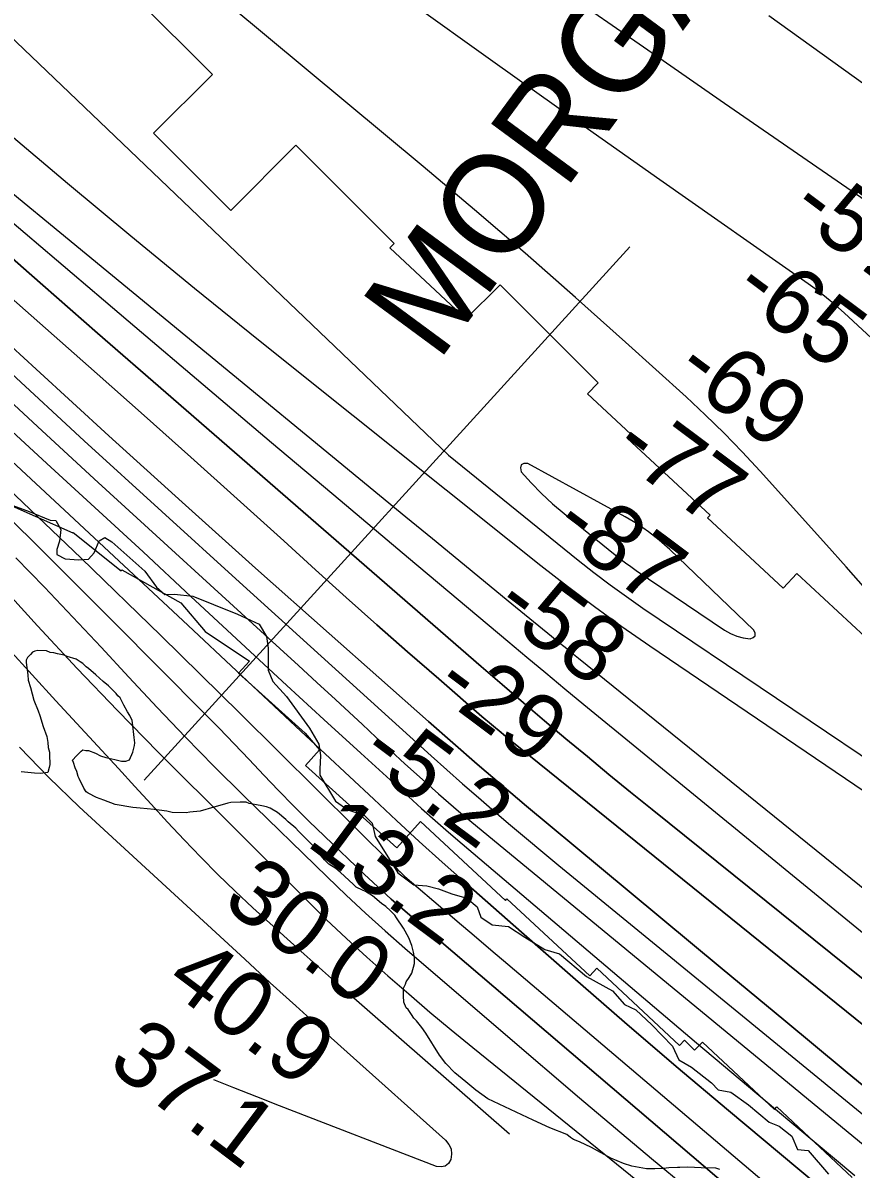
# Model space of a CAD drawing. Extents: x 3187622 to 3225504, y 800805 to 826213.
# Drawn here: x 3200680 to 3201516, y 814862 to 816017 of the extents above; entities that cross this region are included whole.
import ezdxf

# ---------------------------------------------------------------- set-up
doc = ezdxf.new("R2010")
doc.units = 0
for name, color, linetype in [('V-RIVR-EDGE', 7, 'Continuous'), ('V-RIVR-RANG', 7, 'Continuous'), ('V-RRAP-RVMT', 7, 'Continuous'), ('V-SITE-VEGE', 7, 'Continuous'), ('V-TOPO-DPTH', 7, 'Continuous'), ('V-TOPO-GNAM-IDEN', 7, 'Continuous'), ('V-TOPO-MAJR', 7, 'Continuous'), ('V-TOPO-MINR', 7, 'Continuous'), ('V-TOPO-WATR', 7, 'Continuous')]:
    doc.layers.add(name, color=color, linetype=linetype)

msp = doc.modelspace()

# ---------------------------------------------------------------- linework, layer by layer
at = {"layer": 'V-RIVR-EDGE'}
for points in [[(3200646.3, 815538.9), (3200685.8, 815524.5), (3200707.1, 815515.8), (3200712.8, 815515.3), (3200718, 815506.2), (3200716.6, 815494.4), (3200714, 815486.2), (3200714, 815481), (3200722.2, 815476.6), (3200736.1, 815475.7), (3200745.7, 815476.5), (3200751.4, 815482.6), (3200756.6, 815494.8), (3200762.3, 815498.2), (3200769.2, 815493.9), (3200802.6, 815464.2), (3200814.3, 815448.1), (3200822.5, 815440.7), (3200832.5, 815441.1), (3200850.8, 815438.9)], [(3200850.8, 815438.9), (3200871.6, 815430.6), (3200896, 815421), (3200917.7, 815410.9), (3200925, 815398.3), (3200926.7, 815386.5), (3200926.7, 815364.4), (3200931.4, 815353.1), (3200945.3, 815337.8), (3200968.3, 815306), (3200977.8, 815289.9), (3200979.5, 815278.6), (3200979, 815264.7), (3200979, 815258.6), (3200994.6, 815232.5), (3201007.2, 815223.8), (3201023.7, 815218.1), (3201031.5, 815210.2), (3201034.5, 815196.8), (3201057.5, 815160.2), (3201073.5, 815148), (3201086.5, 815147.1), (3201098.3, 815144), (3201111.7, 815139.2), (3201126.9, 815134.8), (3201137.3, 815126.1), (3201141.2, 815115.6), (3201152.5, 815107.8), (3201169, 815106), (3201185.5, 815095.5), (3201205.5, 815082.9), (3201220.3, 815078.5), (3201247.6, 815055.8), (3201273.6, 815041.4), (3201285.8, 815027.5), (3201297.1, 815022.2), (3201313.5, 815007), (3201334.3, 814985.6), (3201340.4, 814971.7), (3201353.4, 814964.3), (3201373.4, 814948.6), (3201380.3, 814941.6), (3201392.9, 814939), (3201410.7, 814926.3), (3201431.5, 814908.9), (3201441.5, 814905), (3201454.5, 814894.9), (3201460.1, 814881.4), (3201471, 814880.5), (3201491.4, 814856.6)]]:
    msp.add_lwpolyline(points, dxfattribs=at)
at = {"layer": 'V-RIVR-RANG'}
msp.add_line((3200801.9, 815253.6), (3201291.3, 815791.3), dxfattribs=at)
at = {"layer": 'V-RRAP-RVMT'}
for p, q in [((3200870.7, 815965), (3200793.6, 816042.1)), ((3200811.3, 815905.6), (3200870.7, 815965)), ((3200889.1, 815827.8), (3200811.3, 815905.6)), ((3200954.7, 815893.5), (3200889.1, 815827.8)), ((3201053.8, 815794.5), (3200954.7, 815893.5)), ((3201049.2, 815790), (3201053.8, 815794.5)), ((3201126, 815718.6), (3201049.2, 815790)), ((3201160.4, 815753), (3201126, 815718.6)), ((3201259.4, 815654.1), (3201160.4, 815753)), ((3201248.4, 815643.1), (3201259.4, 815654.1)), ((3201292.2, 815602.3), (3201248.4, 815643.1)), ((3201288.6, 815598.4), (3201292.2, 815602.3)), ((3201372, 815520.7), (3201288.6, 815598.4)), ((3200582.6, 815568.1), (3200730.1, 815503)), ((3201369.6, 815518.1), (3201372, 815520.7)), ((3201445.6, 815447.1), (3201369.6, 815518.1)), ((3200730.1, 815503), (3200730.2, 815503.3)), ((3200730.2, 815503.3), (3200778.6, 815464.7)), ((3200778.6, 815464.7), (3200779.4, 815465.6)), ((3200779.4, 815465.6), (3200838.7, 815432.5)), ((3201459.5, 815462), (3201445.6, 815447.1)), ((3201542.9, 815384.3), (3201459.5, 815462)), ((3200838.7, 815432.5), (3200863.4, 815403.3)), ((3200863.4, 815403.3), (3200908, 815373.6)), ((3200908, 815373.6), (3200897, 815361.6)), ((3200897, 815361.6), (3200964.2, 815300.9)), ((3200964.2, 815300.9), (3200978.6, 815284.2)), ((3200978.6, 815284.2), (3200964.3, 815268.3)), ((3200964.3, 815268.3), (3201056.3, 815185.3)), ((3201056.3, 815185.3), (3201080.4, 815212)), ((3201080.4, 815212), (3201165.8, 815132.4)), ((3201165.8, 815132.4), (3201167.4, 815134.1)), ((3201167.4, 815134.1), (3201250.8, 815056.4)), ((3201250.8, 815056.4), (3201257.9, 815064)), ((3201257.9, 815064), (3201341.2, 814986.2)), ((3201341.2, 814986.2), (3201346.3, 814991.7)), ((3201346.3, 814991.7), (3201356.5, 814981.5)), ((3201356.5, 814981.5), (3201364.5, 814989.5)), ((3201364.5, 814989.5), (3201437.1, 814921.8)), ((3201437.1, 814921.8), (3201439.3, 814924.2)), ((3201439.3, 814924.2), (3201515.3, 814853.3))]:
    msp.add_line(p, q, dxfattribs=at)
at = {"layer": 'V-SITE-VEGE'}
for points in [[(3201073.2, 815080.4), (3201071.4, 815087.1), (3201068.5, 815094.6), (3201063.2, 815104.5), (3201056.1, 815115), (3201054.3, 815117.5), (3201050.1, 815121.9), (3201045.2, 815126.3), (3201041, 815129.4), (3201032, 815136.9), (3201024.7, 815141.4), (3201021.7, 815142.6), (3201015.6, 815145.8), (3201012.6, 815148.3), (3200999.3, 815160.8), (3200995.1, 815164.6), (3200987.9, 815169), (3200983.6, 815173.4), (3200978.9, 815179), (3200972.3, 815187.1), (3200957.2, 815202.1), (3200954.8, 815205.2), (3200947, 815211.5), (3200944.6, 815214), (3200936.2, 815220.9), (3200928.9, 815225.3), (3200925.2, 815226.6), (3200920.4, 815227.9), (3200914.9, 815228.7), (3200907.5, 815230), (3200904.5, 815231.3), (3200898.4, 815231.4), (3200889.2, 815231), (3200886.1, 815230.4), (3200880.5, 815228.7), (3200871.9, 815226.4), (3200858.4, 815222.4), (3200847.9, 815221.4), (3200844.2, 815220.8), (3200830.2, 815221.1), (3200824.7, 815222.4), (3200811.8, 815223.9), (3200797.8, 815225.4), (3200790.4, 815226.2), (3200772.7, 815229), (3200761.1, 815233.5), (3200753.8, 815236.1), (3200745.4, 815240.5), (3200743.5, 815241.8), (3200741.2, 815245.5), (3200736.4, 815255.4), (3200735.3, 815257.2), (3200734.1, 815262.2), (3200732.4, 815265.9), (3200730.6, 815271.4), (3200729.5, 815273.9), (3200733.8, 815278.1), (3200738.2, 815282.9), (3200740.1, 815284.1), (3200743.1, 815283.4), (3200745.6, 815283.4), (3200752.9, 815280.8), (3200757.7, 815278.3), (3200763.2, 815276.3), (3200772.4, 815274.3), (3200779.1, 815272.9), (3200783.4, 815272.9), (3200787.1, 815274), (3200790.3, 815281.9), (3200792.2, 815288.6), (3200792.3, 815291.1), (3200791.8, 815296.6), (3200790.2, 815311.3), (3200789.7, 815313.8), (3200787.3, 815318.7), (3200784.9, 815322.5), (3200781.4, 815329.3), (3200777.8, 815336.7), (3200775.4, 815338.6), (3200773.6, 815341.1), (3200769.4, 815345.4), (3200765.8, 815348.6), (3200760.4, 815353), (3200753.2, 815359.8), (3200745.9, 815366.1), (3200743.5, 815368), (3200739.9, 815371.1), (3200737.5, 815373), (3200733.3, 815375.6), (3200724.1, 815378.2), (3200721.1, 815379.5), (3200714.4, 815380.8), (3200710.7, 815382.1), (3200707, 815382.2), (3200703.4, 815384.1), (3200694.8, 815384.3), (3200691.7, 815383.7), (3200689.3, 815382.5), (3200687.4, 815380.1), (3200684.3, 815377.1), (3200683, 815374.7)], [(3200683, 815374.7), (3200682.9, 815372.2), (3200683.5, 815367.3), (3200684.5, 815359.9), (3200685, 815354.4), (3200687.4, 815347), (3200690.8, 815334.1), (3200694.9, 815323.6), (3200696.6, 815318.7), (3200700.1, 815307.6), (3200703.6, 815297.7), (3200704.7, 815291.5), (3200705.2, 815286.6), (3200706.3, 815281.7), (3200706.3, 815279.3), (3200706.7, 815269.4), (3200706, 815266.4), (3200704.7, 815261.5), (3200697.3, 815260.4), (3200691.2, 815260.6), (3200677.8, 815262)], [(3201382, 814861.2), (3201377.8, 814862.5), (3201363.1, 814862.8), (3201349.6, 814863.6), (3201341.6, 814863.2), (3201339.2, 814863.2), (3201330.6, 814862.8), (3201325.1, 814862.3), (3201316.5, 814861.8), (3201307.9, 814862), (3201293.3, 814864.7), (3201284.7, 814867.3), (3201272, 814872.5), (3201258.6, 814880.1), (3201252.6, 814883.3), (3201240.4, 814889), (3201234.3, 814891.6), (3201231.3, 814893.5), (3201227.7, 814896.6), (3201210.7, 814903.1), (3201193.7, 814910.8), (3201148.1, 814932.5), (3201136, 814941.3), (3201125.8, 814949.4), (3201114.9, 814958.8), (3201105.9, 814968.2), (3201099.3, 814976.3), (3201085.7, 814998.6), (3201081.5, 815004.2), (3201076.1, 815011.1), (3201073.7, 815013.6), (3201071.3, 815017.3), (3201067.7, 815022.3), (3201065.9, 815024.1), (3201063.6, 815029.7), (3201063.1, 815036.4), (3201063.3, 815043.8), (3201065.2, 815048.1), (3201065.8, 815050.5), (3201069, 815054.7), (3201071.5, 815059), (3201074.2, 815068.7), (3201074.3, 815074.8), (3201073.2, 815080.4)]]:
    msp.add_lwpolyline(points, dxfattribs=at)
at = {"layer": 'V-TOPO-DPTH'}
for points in [[(3201832.3, 814693.5), (3201508.2, 814960.8), (3201446.2, 815012), (3201384.2, 815063.3), (3201322.4, 815114.7), (3201260.6, 815166.2), (3201187.2, 815227.4), (3201162.3, 815248.5), (3201137.4, 815269.7), (3201112.7, 815291.1), (3201088.2, 815312.6), (3200988.3, 815401.3), (3200914.1, 815467.4), (3200840.1, 815533.9), (3200766.4, 815600.7), (3200693, 815667.8), (3200444.1, 815896.4)], [(3200444.1, 815896.4), (3200693, 815667.8), (3200766.4, 815600.7), (3200840.1, 815533.9), (3200914.1, 815467.4), (3200988.3, 815401.3), (3201088.2, 815312.6), (3201112.7, 815291.1), (3201137.4, 815269.7), (3201162.3, 815248.5), (3201187.2, 815227.4), (3201260.6, 815166.2), (3201322.4, 815114.7), (3201384.2, 815063.3), (3201446.2, 815012), (3201508.2, 814960.8), (3201832.3, 814693.5)], [(3201917.2, 814738.5), (3201313.7, 815223.9), (3201291.9, 815241.6), (3201270.1, 815259.4), (3201248.4, 815277.3), (3201226.8, 815295.3), (3201205.3, 815313.4), (3201183.9, 815331.6), (3201162.6, 815349.9), (3201141.3, 815368.3), (3200892.8, 815584.1), (3200823.8, 815644.2), (3200754.9, 815704.3), (3200686.1, 815764.6), (3200617.4, 815824.9)], [(3200617.4, 815824.9), (3200686.1, 815764.6), (3200754.9, 815704.3), (3200823.8, 815644.2), (3200892.8, 815584.1), (3201141.3, 815368.3), (3201162.6, 815349.9), (3201183.9, 815331.6), (3201205.3, 815313.4), (3201226.8, 815295.3), (3201248.4, 815277.3), (3201270.1, 815259.4), (3201291.9, 815241.6), (3201313.7, 815223.9), (3201917.2, 814738.5)], [(3201740.8, 814833.7), (3201180.8, 815285.7), (3201171, 815293.6), (3201161.4, 815301.6), (3201151.8, 815309.7), (3201142.2, 815317.9), (3201098.6, 815355.6), (3201067.3, 815382.8), (3201036.2, 815410.2), (3201005.3, 815437.8), (3200974.6, 815465.5), (3200942.5, 815494.7), (3200895.7, 815537.1), (3200848.8, 815579.3), (3200801.7, 815621.3), (3200754.5, 815663.1), (3200659.1, 815747.4)], [(3200659.1, 815747.4), (3200754.5, 815663.1), (3200801.7, 815621.3), (3200848.8, 815579.3), (3200895.7, 815537.1), (3200942.5, 815494.7), (3200974.6, 815465.5), (3201005.3, 815437.8), (3201036.2, 815410.2), (3201067.3, 815382.8), (3201098.6, 815355.6), (3201142.2, 815317.9), (3201151.8, 815309.7), (3201161.4, 815301.6), (3201171, 815293.6), (3201180.8, 815285.7), (3201740.8, 814833.7)], [(3201760.5, 814611.1), (3201390.7, 814920.7), (3201338, 814965.1), (3201285.7, 815009.8), (3201233.7, 815054.9), (3201181.9, 815100.3), (3201125.6, 815150), (3201102.2, 815170.9), (3201079, 815191.8), (3201056, 815213), (3201033.1, 815234.3), (3200959.8, 815303.1), (3200900.4, 815358.8), (3200840.8, 815414.5), (3200781.2, 815470.1), (3200721.5, 815525.6), (3200566.6, 815669.5)], [(3200566.6, 815669.5), (3200721.5, 815525.6), (3200781.2, 815470.1), (3200840.8, 815414.5), (3200900.4, 815358.8), (3200959.8, 815303.1), (3201033.1, 815234.3), (3201056, 815213), (3201079, 815191.8), (3201102.2, 815170.9), (3201125.6, 815150), (3201181.9, 815100.3), (3201233.7, 815054.9), (3201285.7, 815009.8), (3201338, 814965.1), (3201390.7, 814920.7), (3201760.5, 814611.1)], [(3200642.7, 815657.7), (3200699, 815605.6), (3200755.4, 815553.7), (3200938.6, 815386.3), (3200957.3, 815369.3), (3200975.9, 815352.1), (3200994.5, 815334.9), (3201013, 815317.7), (3201021.4, 815309.9), (3201035.7, 815296.6), (3201050.1, 815283.4), (3201064.6, 815270.2), (3201079.1, 815257.1), (3201098.4, 815239.8), (3201103.4, 815235.4), (3201108.4, 815231), (3201113.4, 815226.8), (3201118.5, 815222.5), (3201720.6, 814726.1)], [(3200642.7, 815657.7), (3200699, 815605.6), (3200755.4, 815553.7), (3200938.6, 815386.3), (3200957.3, 815369.3), (3200975.9, 815352.1), (3200994.5, 815334.9), (3201013, 815317.7), (3201021.4, 815309.9), (3201035.7, 815296.6), (3201050.1, 815283.4), (3201064.6, 815270.2), (3201079.1, 815257.1), (3201098.4, 815239.8), (3201103.4, 815235.4), (3201108.4, 815231), (3201113.4, 815226.8), (3201118.5, 815222.5), (3201720.6, 814726.1)], [(3201392.6, 814841.7), (3201060.2, 815125.7), (3201050.8, 815133.8), (3201041.6, 815142), (3201032.5, 815150.4), (3201023.5, 815158.9), (3200983.4, 815197.2), (3200967.8, 815212.3), (3200952.4, 815227.6), (3200937.3, 815243.1), (3200922.4, 815258.8), (3200907.5, 815274.6), (3200892.5, 815290.3), (3200877.4, 815305.9), (3200862.2, 815321.3), (3200772.1, 815412.1), (3200711.6, 815472.7), (3200650.6, 815532.8)]]:
    msp.add_lwpolyline(points, dxfattribs=at)
at = {"layer": 'V-TOPO-MAJR'}
for points in [[(3201937.8, 815583.1), (3201904.7, 815618), (3201871.4, 815652.6), (3201837.8, 815686.9), (3201803.9, 815720.9), (3201795.1, 815729.7), (3201765.1, 815758.8), (3201734.7, 815787.5), (3201703.5, 815815.4), (3201672, 815842.7), (3201622.8, 815884.3), (3201615.4, 815890.5), (3201607.9, 815896.5), (3201600.2, 815902.3), (3201592.5, 815908), (3201431.4, 816024)], [(3200507.9, 815952.9), (3200792.6, 815710.9), (3200861.4, 815652.4), (3200930.2, 815594.1), (3200999.2, 815535.9), (3201068.2, 815477.8), (3201168.2, 815393.7), (3201187.3, 815377.7), (3201206.5, 815361.7), (3201225.7, 815345.8), (3201245, 815330), (3201419.8, 815186.7), (3201508.8, 815113.8), (3201597.9, 815041.1), (3201687.1, 814968.5), (3201776.4, 814896), (3201910.8, 814787.1)], [(3200665.1, 815386), (3200712.9, 815333.6), (3200775.9, 815265.2), (3200792.4, 815247.3), (3200809, 815229.3), (3200825.5, 815211.4), (3200842.1, 815193.5), (3200858.9, 815175.9), (3200876, 815158.5), (3200893.5, 815141.6), (3200911.4, 815125), (3200963.1, 815078.4), (3200972.2, 815070.2), (3200981.4, 815061.9), (3200990.7, 815053.8), (3201000, 815045.6), (3201170, 814897)]]:
    msp.add_lwpolyline(points, dxfattribs=at)
at = {"layer": 'V-TOPO-MINR'}
for points in [[(3201529, 815446.1), (3201509.2, 815468.6), (3201489.3, 815490.9), (3201422.5, 815565.2), (3201404.5, 815584.5), (3201386.2, 815603.5), (3201367.2, 815621.9), (3201347.9, 815640), (3201286.9, 815695), (3201236.6, 815740), (3201185.8, 815784.6), (3201134.6, 815828.5), (3201083, 815872), (3200691.4, 816198.3)], [(3200596.2, 816071.1), (3201108.5, 815581.1), (3201239.1, 815475.5), (3201255, 815462.9), (3201271.2, 815450.6), (3201287.7, 815438.7), (3201304.4, 815427.1), (3201573.5, 815245.4)], [(3201945, 815411.1), (3201902.3, 815458.7), (3201860, 815506.6), (3201817.1, 815555.8), (3201796.5, 815579.4), (3201775.9, 815602.9), (3201755.3, 815626.5), (3201734.7, 815650), (3201713.6, 815673.1), (3201692, 815695.6), (3201669.5, 815717.3), (3201646.4, 815738.3), (3201569.1, 815806.1), (3201559.4, 815814.2), (3201549.6, 815822.2), (3201539.5, 815829.8), (3201529.3, 815837.1), (3201386.5, 815935.7), (3201304.9, 815992.4), (3201223.3, 816049.1)], [(3201566.6, 815669.6), (3201507.2, 815724.6), (3201498.5, 815732.4), (3201489.5, 815739.9), (3201480.3, 815747), (3201470.8, 815753.9), (3201321.3, 815858.8), (3201237.1, 815918.1), (3201153.1, 815977.8), (3201069.4, 816037.9)], [(3200568.9, 815927.5), (3201065.6, 815519.1), (3201092.3, 815497.2), (3201119, 815475.2), (3201145.7, 815453.3), (3201172.4, 815431.4), (3201212.3, 815398.6), (3201219.1, 815393.1), (3201225.9, 815387.5), (3201232.6, 815382), (3201239.4, 815376.5), (3201898.4, 814844.2)], [(3200661.4, 815908.9), (3200724.7, 815855.3), (3200788.4, 815802.2), (3200852.5, 815749.6), (3200917.1, 815697.5), (3201201.4, 815470), (3201228.3, 815449), (3201255.5, 815428.5), (3201283.2, 815408.6), (3201311.2, 815389.1), (3201744.1, 815095.3), (3201797.3, 815061.5), (3201851.7, 815029.8), (3201907.8, 815001.4), (3201965.1, 814975.1)], [(3200444.1, 815896.4), (3200693, 815667.8), (3200766.4, 815600.7), (3200840.1, 815533.9), (3200914.1, 815467.4), (3200988.3, 815401.3), (3201088.2, 815312.6), (3201112.7, 815291.1), (3201137.4, 815269.7), (3201162.3, 815248.5), (3201187.2, 815227.4), (3201260.6, 815166.2), (3201322.4, 815114.7), (3201384.2, 815063.3), (3201446.2, 815012), (3201508.2, 814960.8), (3201832.3, 814693.5)], [(3200617.4, 815824.9), (3200686.1, 815764.6), (3200754.9, 815704.3), (3200823.8, 815644.2), (3200892.8, 815584.1), (3201141.3, 815368.3), (3201162.6, 815349.9), (3201183.9, 815331.6), (3201205.3, 815313.4), (3201226.8, 815295.3), (3201248.4, 815277.3), (3201270.1, 815259.4), (3201291.9, 815241.6), (3201313.7, 815223.9), (3201917.2, 814738.5)], [(3200659.1, 815747.4), (3200754.5, 815663.1), (3200801.7, 815621.3), (3200848.8, 815579.3), (3200895.7, 815537.1), (3200942.5, 815494.7), (3200974.6, 815465.5), (3201005.3, 815437.8), (3201036.2, 815410.2), (3201067.3, 815382.8), (3201098.6, 815355.6), (3201142.2, 815317.9), (3201151.8, 815309.7), (3201161.4, 815301.6), (3201171, 815293.6), (3201180.8, 815285.7), (3201740.8, 814833.7)], [(3200663.9, 815667.5), (3200741.5, 815595.7), (3200819.5, 815524.3), (3200897.8, 815453.2), (3201090.9, 815278.2), (3201106.7, 815264.1), (3201122.6, 815250), (3201138.6, 815236), (3201154.7, 815222.1), (3201170.8, 815208.4), (3201187.1, 815194.7), (3201203.4, 815181.1), (3201219.8, 815167.6), (3201837.9, 814661.2)], [(3200642.7, 815657.7), (3200699, 815605.6), (3200755.4, 815553.7), (3200938.6, 815386.3), (3200957.3, 815369.3), (3200975.9, 815352.1), (3200994.5, 815334.9), (3201013, 815317.7), (3201021.4, 815309.9), (3201035.7, 815296.6), (3201050.1, 815283.4), (3201064.6, 815270.2), (3201079.1, 815257.1), (3201098.4, 815239.8), (3201103.4, 815235.4), (3201108.4, 815231), (3201113.4, 815226.8), (3201118.5, 815222.5), (3201720.6, 814726.1)], [(3200655.1, 815617.4), (3200703.7, 815572.9), (3200752.2, 815528.3), (3200800.7, 815483.6), (3200849, 815438.7), (3200871.6, 815417.7), (3200908.6, 815383.4), (3200945.7, 815349.1), (3200982.8, 815314.9), (3201020.1, 815280.9), (3201068.1, 815237), (3201081.4, 815225), (3201094.9, 815213), (3201108.4, 815201.2), (3201122.1, 815189.5), (3201358.5, 814989), (3201438.1, 814922), (3201517.9, 814855.3)], [(3201398.9, 815398.7), (3201405.5, 815397.1), (3201412.3, 815396.1), (3201415.4, 815397.3), (3201417.3, 815399.1), (3201417.3, 815401.7), (3201416.1, 815404.8), (3201331.4, 815486.1), (3201320.9, 815495.4), (3201310, 815504), (3201298.5, 815511.8), (3201286.5, 815519), (3201188.5, 815572.9), (3201184.3, 815572.8), (3201181.6, 815571.5), (3201180.9, 815568.5), (3201181.6, 815564.4), (3201191.8, 815553.2), (3201202.3, 815542.4), (3201213.4, 815532.1), (3201224.9, 815522.3), (3201276.5, 815480.6), (3201281.6, 815476.6), (3201286.8, 815472.6), (3201292.1, 815468.8), (3201297.5, 815465), (3201386.7, 815404.8), (3201392.7, 815401.4), (3201398.9, 815398.7)], [(3200657.5, 815554.5), (3200738.4, 815477.2), (3200818.7, 815399.3), (3200898.5, 815320.8), (3201053.1, 815167.6), (3201055.3, 815165.5), (3201057.5, 815163.3), (3201059.8, 815161.1), (3201062, 815159), (3201064.3, 815156.9), (3201066.6, 815154.8), (3201068.9, 815152.7), (3201071.3, 815150.7), (3201100.4, 815125.9), (3201117.3, 815111.5), (3201134.3, 815097.1), (3201151.2, 815082.7), (3201168.2, 815068.3), (3201682.3, 814631.4)], [(3200650.6, 815532.8), (3200711.6, 815472.7), (3200772.1, 815412.1), (3200862.2, 815321.3), (3200877.4, 815305.9), (3200892.5, 815290.3), (3200907.5, 815274.6), (3200922.4, 815258.8), (3200937.3, 815243.1), (3200952.4, 815227.6), (3200967.8, 815212.3), (3200983.4, 815197.2), (3201023.5, 815158.9), (3201032.5, 815150.4), (3201041.6, 815142), (3201050.8, 815133.8), (3201060.2, 815125.7), (3201392.6, 814841.7)], [(3200672.5, 815477.8), (3200701.4, 815448), (3200730, 815418), (3200758.4, 815387.7), (3200786.5, 815357.3), (3200814.8, 815326.9), (3200843.4, 815296.8), (3200872.5, 815267.3), (3200902, 815238.1), (3200986.3, 815156.1), (3201005.5, 815137.8), (3201024.9, 815119.7), (3201044.6, 815101.9), (3201064.6, 815084.4), (3201168.2, 814995.1), (3201240.4, 814933.5), (3201313, 814872.3), (3201386.2, 814811.9)], [(3200654.8, 815452.4), (3200694.3, 815409), (3200734.2, 815366), (3200774.9, 815323.7), (3200816.1, 815281.9), (3200965.3, 815132.9), (3200985.3, 815113.3), (3201005.6, 815094), (3201026.3, 815075.1), (3201047.2, 815056.4), (3201068.4, 815038.1), (3201089.7, 815019.9), (3201111.2, 815002), (3201132.9, 814984.2), (3201708.2, 814518.3)], [(3200676.1, 815287), (3200705.8, 815256.3), (3200736.5, 815226.6), (3200903.1, 815073.1), (3200928.8, 815049.5), (3200954.5, 815026.1), (3200980.4, 815002.7), (3201006.3, 814979.4), (3201105.4, 814890.8), (3201108.8, 814886.5), (3201111, 814881.9), (3201111.5, 814876.8), (3201110.9, 814871.4), (3201108.4, 814867.4), (3201105.2, 814864.7), (3201101.1, 814863.8), (3201096.4, 814864.3), (3200938.2, 814925.3), (3200915.2, 814934.3), (3200892.3, 814943.4), (3200872.1, 814951.5)]]:
    msp.add_lwpolyline(points, dxfattribs=at)
at = {"layer": 'V-TOPO-WATR'}
msp.add_lwpolyline([(3200566.6, 815669.5), (3200721.5, 815525.6), (3200781.2, 815470.1), (3200840.8, 815414.5), (3200900.4, 815358.8), (3200959.8, 815303.1), (3201033.1, 815234.3), (3201056, 815213), (3201079, 815191.8), (3201102.2, 815170.9), (3201125.6, 815150), (3201181.9, 815100.3), (3201233.7, 815054.9), (3201285.7, 815009.8), (3201338, 814965.1), (3201390.7, 814920.7), (3201760.5, 814611.1)], dxfattribs=at)

# ---------------------------------------------------------------- texts
at = {"layer": 'V-RIVR-RANG'}
for s, rotation, p in [('-57', 323.243, (3201449.9, 815824.3)), ('-65', 323.243, (3201392.4, 815742.4)), ('-69', 323.243, (3201333.8, 815661.3)), ('-77', 323.243, (3201271, 815583.4)), ('-87', 323.243, (3201210.6, 815503.7)), ('-58', 323.243, (3201151.4, 815423.1)), ('-29', 323.243, (3201091.2, 815343.3)), ('-5.2', 323.243, (3201016.1, 815274.5)), ('13.2', 323.243, (3200963.7, 815188.9)), ('30.0', 322.9683, (3200878.9, 815128.1)), ('40.9', 322.9683, (3200821, 815046.5)), ('37.1', 322.9683, (3200763.1, 814965))]:
    msp.add_text(s, height=67, rotation=rotation, dxfattribs=at).set_placement(p)
at = {"layer": 'V-TOPO-GNAM-IDEN'}
msp.add_text('MORGANZA LDG.', height=100, rotation=53.5919, dxfattribs=at).set_placement((3201097.6, 815673.7))

doc.saveas('drawing.dxf')
